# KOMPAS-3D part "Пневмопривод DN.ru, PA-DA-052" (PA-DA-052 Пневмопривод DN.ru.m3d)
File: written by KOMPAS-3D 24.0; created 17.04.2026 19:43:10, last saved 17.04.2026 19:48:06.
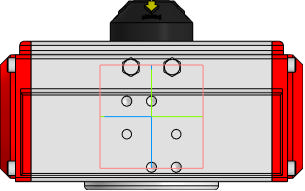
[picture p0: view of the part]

Document properties: Автор: DN.ru; Полное имя файла: C:\Работа\PA-DA-х Пневмопривод DN.ru\052\PA-DA-052 Пневмопривод DN.ru.m3d

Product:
- Part/product: Пневмопривод DN.ru  | designation PA-DA-052
    Масса: 1.4
    Раздел спецификации: Прочие изделия
    Примечание: D290-00293

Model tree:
1. Операция без истории:1

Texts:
  PA-DA-052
